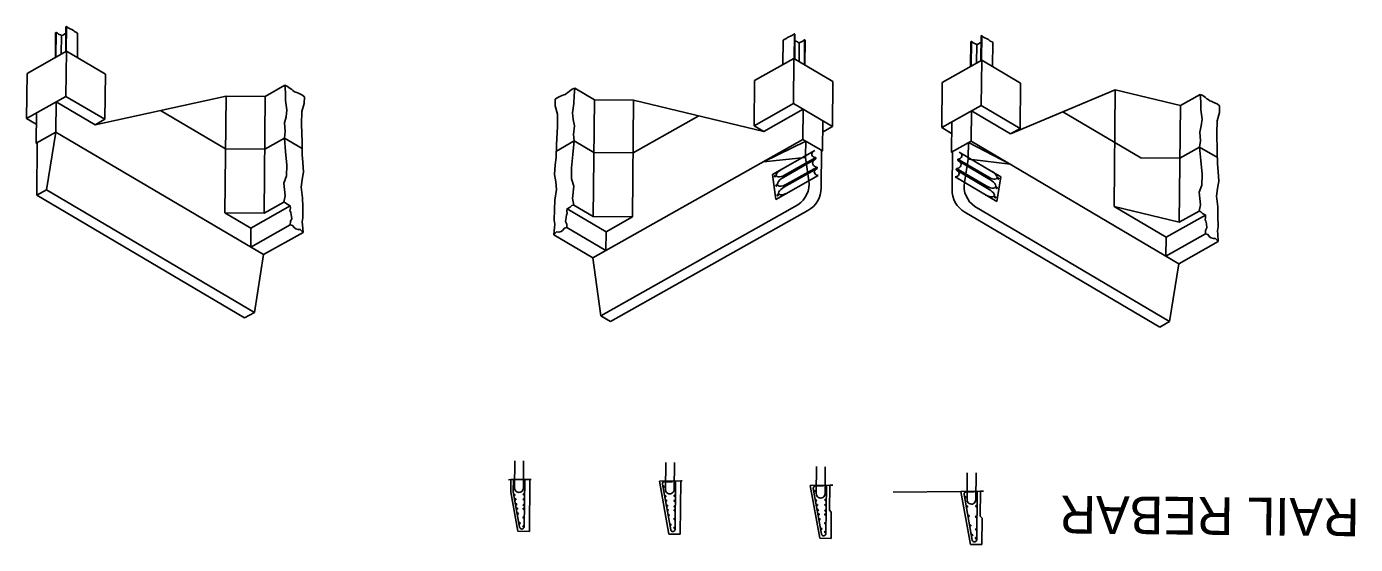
# Model space of a CAD drawing. Extents: x 631918 to 632319, y 373181 to 373282.
# Drawn here: x 631918.3 to 632006.4, y 373247.3 to 373281.7 of the extents above; entities that cross this region are included whole.
import ezdxf

# ---------------------------------------------------------------- set-up
doc = ezdxf.new("R2010")
doc.units = 0
for name, color, linetype in [('B_Boring', 7, 'Continuous'), ('BD-PROP-COSS', 7, 'Continuous'), ('BD-REMOVE', 7, 'Continuous'), ('R_Border_Scale', 7, 'Continuous'), ('R_Proposed Const Limits Cut', 7, 'Continuous'), ('R_Road Edge of Travel', 7, 'Continuous'), ('R_Shade Removal', 7, 'Continuous')]:
    doc.layers.add(name, color=color, linetype=linetype)

msp = doc.modelspace()

# ---------------------------------------------------------------- linework, layer by layer
at = {"layer": 'B_Boring'}
for p, q in [((631969.792, 373272.95), (631969.934, 373272.964)), ((631969.934, 373272.964), (631969.935, 373273.03)), ((631970.151, 373271.419), (631969.934, 373272.964)), ((631980.469, 373271.316), (631980.716, 373272.857)), ((631980.716, 373272.857), (631980.717, 373272.922)), ((631980.858, 373272.84), (631980.716, 373272.857))]:
    msp.add_line(p, q, dxfattribs=at)
at = {"layer": 'BD-PROP-COSS'}
for p, q in [((631950.664, 373252.836), (631950.646, 373251.044)), ((631951.247, 373252.83), (631951.229, 373251.038)), ((631960.663, 373252.736), (631960.645, 373250.945)), ((631961.247, 373252.73), (631961.229, 373250.939)), ((631970.661, 373252.454), (631970.643, 373250.663)), ((631971.244, 373252.449), (631971.226, 373250.657)), ((631980.657, 373252.052), (631980.64, 373250.261)), ((631981.241, 373252.047), (631981.223, 373250.255)), ((631950.56, 373250.791), (631950.568, 373251.599)), ((631951.287, 373248.474), (631951.318, 373251.591)), ((631960.452, 373251.286), (631960.996, 373248.267)), ((631961.121, 373251.452), (631960.597, 373251.457)), ((631961.286, 373248.292), (631961.318, 373251.492)), ((631971.119, 373251.171), (631970.595, 373251.176)), ((631971.283, 373248.01), (631971.315, 373251.21)), ((631950.56, 373250.791), (631950.982, 373248.447)), ((631970.45, 373251.004), (631970.994, 373247.985)), ((631980.447, 373250.602), (631980.991, 373247.583)), ((631981.115, 373250.768), (631980.592, 373250.774)), ((631981.28, 373247.608), (631981.312, 373250.808))]:
    msp.add_line(p, q, dxfattribs=at)
for centre in [(631950.606, 373251.211), (631951.274, 373251.329), (631960.528, 373251.112), (631961.273, 373251.23), (631950.641, 373250.586), (631950.693, 373250.293), (631951.263, 373250.288), (631951.267, 373250.621), (631960.64, 373250.486), (631960.693, 373250.194), (631961.263, 373250.188), (631961.266, 373250.522), (631970.525, 373250.831), (631970.638, 373250.205), (631971.264, 373250.24), (631971.271, 373250.948), (631980.522, 373250.429), (631981.267, 373250.546), (631950.753, 373249.96), (631950.806, 373249.667), (631950.865, 373249.333), (631951.257, 373249.663), (631951.26, 373249.913), (631960.753, 373249.86), (631960.805, 373249.568), (631961.257, 373249.563), (631961.259, 373249.813), (631970.69, 373249.912), (631970.75, 373249.578), (631971.257, 373249.532), (631971.261, 373249.907), (631980.634, 373249.802), (631981.26, 373249.838), (631950.978, 373248.707), (631951.246, 373248.496), (631951.251, 373249.08), (631960.865, 373249.234), (631960.977, 373248.608), (631961.251, 373248.98), (631970.803, 373249.286), (631970.863, 373248.952), (631971.249, 373248.698), (631971.254, 373249.282), (631980.747, 373249.176), (631980.859, 373248.55), (631981.253, 373249.13), (631961.245, 373248.397), (631970.975, 373248.326), (631971.243, 373248.115), (631980.972, 373247.924), (631981.239, 373247.713), (631981.245, 373248.296)]:
    msp.add_circle(centre, 0.0417, dxfattribs=at)
for centre, radius, start, end in [((631960.596, 373251.312), 0.146, 89.43036, 190.21458), ((631970.594, 373251.03), 0.146, 89.43036, 190.21458), ((631950.938, 373251.041), 0.292, 179.43036, 359.43036), ((631960.937, 373250.942), 0.292, 179.43036, 359.43036), ((631970.935, 373250.66), 0.292, 179.43036, 359.43036), ((631980.59, 373250.628), 0.146, 89.43036, 190.21458), ((631980.931, 373250.258), 0.292, 179.43036, 359.43036), ((631961.14, 373248.293), 0.146, 190.21458, 359.43036), ((631971.138, 373248.011), 0.146, 190.21458, 359.43036), ((631981.134, 373247.609), 0.146, 190.21458, 359.43036)]:
    msp.add_arc(centre, radius, start, end, dxfattribs=at)
msp.add_ellipse((631951.134, 373248.476), major_axis=(-0.002, -0.161), ratio=0.951273, start_param=4.900609, end_param=7.853982, dxfattribs=at)
at = {"layer": 'R_Border_Scale'}
for p, q in [((631931.485, 373273.544), (631927.18, 373276.087)), ((631992.156, 373272.941), (631986.99, 373275.992)), ((631958.498, 373273.275), (631962.853, 373275.732)), ((631934.083, 373273.518), (631935.39, 373274.255)), ((631936.563, 373273.562), (631935.39, 373274.255)), ((631953.422, 373273.395), (631954.608, 373274.064)), ((631955.9, 373273.301), (631954.608, 373274.064)), ((631931.485, 373273.544), (631934.083, 373273.518)), ((631958.498, 373273.275), (631955.9, 373273.301)), ((631994.754, 373272.915), (631996.061, 373273.652)), ((631997.234, 373272.959), (631996.061, 373273.652)), ((631992.156, 373272.941), (631994.754, 373272.915)), ((631950.403, 373251.591), (631951.664, 373251.604)), ((631960.246, 373251.49), (631961.663, 373251.504)), ((631970.244, 373251.209), (631971.536, 373251.222)), ((631980.24, 373250.806), (631981.532, 373250.819))]:
    msp.add_line(p, q, dxfattribs=at)
at = {"layer": 'R_Proposed Const Limits Cut'}
for p, q in [((631967.742, 373271.841), (631970.547, 373273.424)), ((631982.886, 373271.69), (631980.112, 373273.329)), ((631968.467, 373271.649), (631970.626, 373272.867)), ((631968.499, 373270.988), (631970.714, 373272.237)), ((631968.547, 373271.794), (631970.613, 373272.96)), ((631968.715, 373271.21), (631970.701, 373272.33)), ((631970.626, 373272.867), (631970.613, 373272.96)), ((631970.714, 373272.237), (631970.701, 373272.33)), ((631979.922, 373272.146), (631979.937, 373272.238)), ((631981.9, 373271.079), (631979.937, 373272.238)), ((631980.023, 373272.773), (631980.038, 373272.866)), ((631982.156, 373271.513), (631980.023, 373272.773)), ((631982.08, 373271.66), (631980.038, 373272.866)), ((631967.974, 373270.19), (631967.742, 373271.841)), ((631967.974, 373270.19), (631970.779, 373271.773)), ((631982.621, 373270.045), (631979.848, 373271.683)), ((631982.112, 373270.852), (631979.922, 373272.146)), ((631982.621, 373270.045), (631982.886, 373271.69))]:
    msp.add_line(p, q, dxfattribs=at)
for centre, major_axis, ratio, start_param, end_param in [((631970.616, 373273.188), (0.267, -0.005), 0.854896, 2.174054, 4.712811), ((631980.038, 373273.094), (0.267, -0.001), 0.854896, 4.711967, 7.250724), ((631970.705, 373272.594), (0.309, -0.005), 0.854896, 2.174054, 4.712811), ((631979.938, 373272.503), (0.309, -0.001), 0.854896, 4.711967, 7.250724), ((631968.44, 373271.984), (-0.44, -0.248), 0.432148, 4.712389, 7.853982), ((631968.591, 373271.43), (-0.508, -0.287), 0.432148, 4.712389, 7.853982), ((631970.783, 373272.002), (0.267, -0.005), 0.854896, 2.174054, 4.712811), ((631979.848, 373271.911), (0.267, -0.001), 0.854896, 4.711967, 7.250724), ((631982.028, 373271.296), (0.502, -0.297), 0.432148, 4.712389, 7.853982), ((631982.191, 373271.847), (0.435, -0.257), 0.432148, 4.712389, 7.853982), ((631968.606, 373270.798), (-0.44, -0.248), 0.432148, 4.712389, 7.853982), ((631982.001, 373270.664), (0.435, -0.257), 0.432148, 4.712389, 7.853982)]:
    msp.add_ellipse(centre, major_axis=major_axis, ratio=ratio, start_param=start_param, end_param=end_param, dxfattribs=at)
for centre, major_axis in [((631967.915, 373271.727), (-0.0216, -0.0437)), ((631968.539, 373271.74), (-0.0216, -0.0437)), ((631982.086, 373271.605), (0.0207, -0.0441)), ((631982.711, 373271.58), (0.0207, -0.0441)), ((631968.003, 373271.098), (-0.0216, -0.0437)), ((631968.091, 373270.468), (-0.0216, -0.0437)), ((631968.628, 373271.11), (-0.0216, -0.0437)), ((631981.985, 373270.978), (0.0207, -0.0441)), ((631982.61, 373270.952), (0.0207, -0.0441)), ((631982.509, 373270.325), (0.0207, -0.0441))]:
    msp.add_ellipse(centre, major_axis=major_axis, ratio=0.68171, dxfattribs=at)
at = {"layer": 'R_Road Edge of Travel'}
for p, q in [((631920.205, 373279.609), (631920.221, 373281.244)), ((631920.246, 373279.632), (631920.262, 373281.267)), ((631920.598, 373279.831), (631920.61, 373281.062)), ((631920.89, 373279.996), (631920.906, 373281.631)), ((631920.931, 373280.019), (631920.947, 373281.654)), ((631921.667, 373279.595), (631921.683, 373281.219)), ((631969.179, 373279.539), (631969.195, 373281.174)), ((631969.219, 373279.515), (631969.236, 373281.15)), ((631981.602, 373279.416), (631981.618, 373281.051)), ((631968.435, 373279.13), (631968.451, 373280.754)), ((631969.508, 373279.345), (631969.52, 373280.575)), ((631969.856, 373279.139), (631969.872, 373280.774)), ((631969.897, 373279.115), (631969.913, 373280.75)), ((631980.876, 373279.006), (631980.892, 373280.641)), ((631980.917, 373279.029), (631980.933, 373280.664)), ((631981.269, 373279.228), (631981.281, 373280.459)), ((631981.561, 373279.392), (631981.577, 373281.028)), ((631982.338, 373278.992), (631982.354, 373280.616))]:
    msp.add_line(p, q, dxfattribs=at)
for points in [[(631920.221, 373281.244), (631920.262, 373281.267), (631920.308, 373281.242), (631920.346, 373281.206), (631920.421, 373281.15), (631920.457, 373281.136), (631920.537, 373281.104), (631920.61, 373281.062), (631920.691, 373281.09), (631920.736, 373281.115), (631920.839, 373281.166), (631920.868, 373281.17), (631920.902, 373281.19)], [(631920.906, 373281.631), (631920.947, 373281.654), (631921.059, 373281.562), (631921.148, 373281.517), (631921.348, 373281.429), (631921.423, 373281.37), (631921.48, 373281.32), (631921.511, 373281.296), (631921.566, 373281.275), (631921.683, 373281.219)], [(631969.236, 373281.15), (631969.195, 373281.174), (631969.081, 373281.085), (631968.992, 373281.041), (631968.79, 373280.957), (631968.714, 373280.9), (631968.656, 373280.851), (631968.624, 373280.828), (631968.569, 373280.808), (631968.451, 373280.754)], [(631981.577, 373281.028), (631981.618, 373281.051), (631981.73, 373280.959), (631981.819, 373280.914), (631982.019, 373280.825), (631982.094, 373280.767), (631982.151, 373280.717), (631982.182, 373280.693), (631982.237, 373280.672), (631982.354, 373280.616)], [(631969.913, 373280.75), (631969.872, 373280.774), (631969.827, 373280.749), (631969.787, 373280.714), (631969.711, 373280.659), (631969.675, 373280.646), (631969.594, 373280.616), (631969.52, 373280.575), (631969.44, 373280.605), (631969.396, 373280.631), (631969.293, 373280.685), (631969.265, 373280.689), (631969.231, 373280.709)], [(631980.892, 373280.641), (631980.933, 373280.664), (631980.978, 373280.638), (631981.017, 373280.602), (631981.092, 373280.546), (631981.128, 373280.533), (631981.208, 373280.5), (631981.281, 373280.459), (631981.362, 373280.487), (631981.407, 373280.512), (631981.51, 373280.563), (631981.539, 373280.567), (631981.573, 373280.586)]]:
    msp.add_lwpolyline(points, dxfattribs=at)
at = {"layer": 'R_Shade Removal'}
for p, q in [((631918.328, 373278.55), (631920.941, 373280.024)), ((631920.911, 373277.024), (631920.941, 373280.024)), ((631923.524, 373278.498), (631920.941, 373280.024)), ((631966.557, 373278.071), (631969.169, 373279.545)), ((631969.14, 373276.545), (631969.169, 373279.545)), ((631971.753, 373278.019), (631969.169, 373279.545)), ((631978.999, 373277.947), (631981.612, 373279.421)), ((631981.582, 373276.421), (631981.612, 373279.421)), ((631984.195, 373277.895), (631981.612, 373279.421)), ((631918.298, 373275.55), (631918.328, 373278.55)), ((631923.494, 373275.499), (631923.524, 373278.498)), ((631934.118, 373277.018), (631935.425, 373277.755)), ((631955.935, 373276.801), (631954.643, 373277.564)), ((631966.527, 373275.071), (631966.557, 373278.071)), ((631971.723, 373275.019), (631971.753, 373278.019)), ((631978.969, 373274.947), (631978.999, 373277.947)), ((631984.165, 373274.895), (631984.195, 373277.895)), ((631918.298, 373275.55), (631920.911, 373277.024)), ((631920.238, 373274.656), (631920.258, 373276.656)), ((631922.841, 373275.13), (631920.258, 373276.656)), ((631923.494, 373275.499), (631920.911, 373277.024)), ((631931.52, 373277.044), (631922.841, 373275.13)), ((631931.52, 373277.044), (631931.443, 373269.294)), ((631931.52, 373277.044), (631934.118, 373277.018)), ((631934.118, 373277.018), (631934.041, 373269.268)), ((631955.935, 373276.801), (631955.858, 373269.052)), ((631958.533, 373276.775), (631955.935, 373276.801)), ((631958.533, 373276.775), (631958.456, 373269.026)), ((631958.533, 373276.775), (631967.173, 373274.689)), ((631990.469, 373277.458), (631983.511, 373274.527)), ((631990.469, 373277.458), (631990.392, 373269.708)), ((631990.469, 373277.458), (631994.789, 373276.415)), ((631994.789, 373276.415), (631996.096, 373277.152)), ((631918.931, 373273.919), (631918.951, 373275.919)), ((631966.527, 373275.071), (631969.14, 373276.545)), ((631967.173, 373274.689), (631969.785, 373276.163)), ((631971.723, 373275.019), (631969.14, 373276.545)), ((631969.766, 373274.164), (631969.785, 373276.163)), ((631978.969, 373274.947), (631981.582, 373276.421)), ((631980.909, 373274.053), (631980.928, 373276.053)), ((631983.511, 373274.527), (631980.928, 373276.053)), ((631984.165, 373274.895), (631981.582, 373276.421)), ((631994.789, 373276.415), (631994.712, 373268.665)), ((631918.944, 373275.169), (631918.298, 373275.55)), ((631922.841, 373275.13), (631923.494, 373275.499)), ((631967.173, 373274.689), (631966.527, 373275.071)), ((631971.057, 373273.401), (631971.077, 373275.401)), ((631971.069, 373274.651), (631971.723, 373275.019)), ((631979.615, 373274.566), (631978.969, 373274.947)), ((631979.602, 373273.316), (631979.622, 373275.316)), ((631983.511, 373274.527), (631984.165, 373274.895)), ((631918.931, 373273.919), (631920.238, 373274.656)), ((631919.622, 373270.829), (631920.238, 373274.656)), ((631934.014, 373266.519), (631920.238, 373274.656)), ((631955.83, 373266.302), (631969.766, 373274.164)), ((631967.153, 373272.689), (631969.945, 373274.058)), ((631971.057, 373273.401), (631969.766, 373274.164)), ((631969.935, 373273.078), (631969.945, 373274.058)), ((631979.602, 373273.316), (631980.909, 373274.053)), ((631994.685, 373265.915), (631980.909, 373274.053)), ((631919.003, 373273.876), (631918.931, 373273.919)), ((631918.969, 373270.46), (631919.004, 373273.96)), ((631970.96, 373270.943), (631970.985, 373273.443)), ((631970.984, 373273.36), (631971.057, 373273.401)), ((631979.674, 373273.273), (631979.602, 373273.316)), ((631979.65, 373270.857), (631979.675, 373273.357)), ((631980.717, 373272.971), (631980.727, 373273.95)), ((631983.492, 373272.527), (631980.727, 373273.95)), ((631967.153, 373272.689), (631969.69, 373272.94)), ((631983.492, 373272.527), (631980.96, 373272.828)), ((631918.969, 373270.46), (631919.622, 373270.829)), ((631933.398, 373262.691), (631919.622, 373270.829)), ((631932.745, 373262.323), (631918.969, 373270.46)), ((631933.165, 373268.277), (631935.778, 373269.751)), ((631934.041, 373269.268), (631935.348, 373270.005)), ((631955.858, 373269.052), (631954.566, 373269.814)), ((631956.369, 373262.463), (631969.434, 373269.833)), ((631994.069, 373262.088), (631981.154, 373269.717)), ((631990.392, 373269.708), (631994.712, 373268.665)), ((631993.836, 373267.674), (631990.392, 373269.708)), ((631933.165, 373268.277), (631931.443, 373269.294)), ((631931.443, 373269.294), (631934.041, 373269.268)), ((631956.714, 373268.043), (631954.131, 373269.569)), ((631958.456, 373269.026), (631955.858, 373269.052)), ((631956.714, 373268.043), (631958.456, 373269.026)), ((631957.015, 373262.081), (631970.08, 373269.452)), ((631993.416, 373261.719), (631980.501, 373269.348)), ((631993.836, 373267.674), (631996.449, 373269.148)), ((631994.712, 373268.665), (631996.019, 373269.402)), ((631933.153, 373267.027), (631935.766, 373268.501)), ((631933.165, 373268.277), (631933.153, 373267.027)), ((631934.014, 373266.519), (631936.627, 373267.993)), ((631956.701, 373266.793), (631954.118, 373268.319)), ((631956.714, 373268.043), (631956.701, 373266.793)), ((631993.836, 373267.674), (631992.114, 373268.691)), ((631993.824, 373266.424), (631996.437, 373267.898)), ((631955.83, 373266.302), (631953.247, 373267.827)), ((631993.836, 373267.674), (631993.824, 373266.424)), ((631994.685, 373265.915), (631997.298, 373267.389)), ((631933.398, 373262.691), (631934.014, 373266.519)), ((631956.369, 373262.463), (631955.83, 373266.302)), ((631994.069, 373262.088), (631994.685, 373265.915)), ((631932.745, 373262.323), (631933.398, 373262.691)), ((631957.015, 373262.081), (631956.369, 373262.463)), ((631993.416, 373261.719), (631994.069, 373262.088)), ((631950.247, 373251.59), (631950.403, 373251.591)), ((631950.395, 373250.768), (631950.403, 373251.591)), ((631951.629, 373248.159), (631951.664, 373251.604)), ((631951.664, 373251.604), (631951.747, 373251.605)), ((631960.246, 373251.49), (631960.878, 373247.984)), ((631961.628, 373247.976), (631961.663, 373251.504)), ((631961.663, 373251.504), (631961.746, 373251.505)), ((631970.244, 373251.209), (631970.876, 373247.702)), ((631971.519, 373249.571), (631971.536, 373251.222)), ((631971.536, 373251.222), (631971.744, 373251.224)), ((631950.395, 373250.768), (631950.864, 373248.167)), ((631975.739, 373250.761), (631980.24, 373250.806)), ((631980.24, 373250.806), (631980.872, 373247.3)), ((631981.516, 373249.169), (631981.532, 373250.819)), ((631981.532, 373250.819), (631981.74, 373250.821)), ((631971.643, 373249.445), (631971.519, 373249.571)), ((631971.626, 373247.695), (631971.643, 373249.445)), ((631981.64, 373249.042), (631981.516, 373249.169)), ((631981.622, 373247.293), (631981.64, 373249.042)), ((631950.864, 373248.167), (631951.629, 373248.159)), ((631960.878, 373247.984), (631961.628, 373247.976)), ((631970.876, 373247.702), (631971.626, 373247.695)), ((631980.872, 373247.3), (631981.622, 373247.293))]:
    msp.add_line(p, q, dxfattribs=at)
for points in [[(631936.627, 373267.993), (631936.442, 373268.192), (631936.306, 373268.194), (631936.146, 373268.235), (631936.051, 373268.3), (631936.051, 373268.3), (631935.933, 373268.461), (631935.933, 373268.461), (631935.766, 373268.501), (631935.784, 373268.716), (631935.873, 373268.91), (631935.873, 373268.91), (631935.836, 373269.166), (631935.806, 373269.334), (631935.759, 373269.431), (631935.784, 373269.598), (631935.778, 373269.751), (631935.579, 373269.864), (631935.46, 373269.962), (631935.46, 373269.962), (631935.348, 373270.005), (631935.438, 373270.433), (631935.362, 373271.26), (631935.529, 373271.74), (631935.55, 373272.468), (631935.461, 373273.364), (631935.39, 373274.255), (631935.447, 373274.68), (631935.4, 373275.255), (631935.498, 373275.674), (631935.558, 373276.121), (631935.467, 373276.738), (631935.459, 373277.27), (631935.425, 373277.755)], [(631936.716, 373276.992), (631936.55, 373277.125), (631936.363, 373277.203), (631936.147, 373277.297), (631936.066, 373277.333), (631935.953, 373277.41), (631935.875, 373277.471), (631935.778, 373277.548), (631935.592, 373277.683), (631935.425, 373277.755)], [(631953.247, 373267.827), (631953.436, 373268.023), (631953.572, 373268.022), (631953.732, 373268.06), (631953.829, 373268.123), (631953.829, 373268.123), (631953.95, 373268.282), (631953.95, 373268.282), (631954.118, 373268.319), (631954.105, 373268.534), (631954.019, 373268.729), (631954.019, 373268.729), (631954.061, 373268.985), (631954.095, 373269.152), (631954.144, 373269.248), (631954.121, 373269.416), (631954.131, 373269.569), (631954.332, 373269.678), (631954.453, 373269.773), (631954.453, 373269.773), (631954.566, 373269.814), (631954.484, 373270.244), (631954.576, 373271.069), (631954.419, 373271.552), (631954.413, 373272.28), (631954.519, 373273.175), (631954.608, 373274.064), (631954.559, 373274.49), (631954.618, 373275.064), (631954.528, 373275.484), (631954.477, 373275.933), (631954.581, 373276.548), (631954.599, 373277.079), (631954.643, 373277.564)], [(631953.337, 373276.827), (631953.506, 373276.956), (631953.694, 373277.03), (631953.912, 373277.121), (631953.994, 373277.155), (631954.108, 373277.23), (631954.188, 373277.289), (631954.286, 373277.364), (631954.475, 373277.495), (631954.643, 373277.564)], [(631936.716, 373276.992), (631936.71, 373276.559), (631936.542, 373276.009), (631936.52, 373275.178), (631936.561, 373273.986), (631936.565, 373273.138), (631936.62, 373272.649), (631936.666, 373271.992), (631936.568, 373271.514), (631936.507, 373271.003), (631936.598, 373270.298), (631936.604, 373269.69), (631936.611, 373268.97), (631936.566, 373268.699), (631936.566, 373268.699), (631936.589, 373268.491), (631936.627, 373267.993)], [(631953.337, 373276.827), (631953.335, 373276.393), (631953.491, 373275.841), (631953.497, 373275.009), (631953.432, 373273.819), (631953.411, 373272.971), (631953.347, 373272.483), (631953.287, 373271.827), (631953.376, 373271.347), (631953.427, 373270.835), (631953.322, 373270.132), (631953.304, 373269.524), (631953.282, 373268.805), (631953.322, 373268.532), (631953.322, 373268.532), (631953.295, 373268.325), (631953.247, 373267.827)], [(631997.298, 373267.389), (631997.113, 373267.589), (631996.977, 373267.59), (631996.817, 373267.632), (631996.722, 373267.697), (631996.722, 373267.697), (631996.604, 373267.858), (631996.604, 373267.858), (631996.437, 373267.898), (631996.454, 373268.113), (631996.544, 373268.306), (631996.544, 373268.306), (631996.507, 373268.563), (631996.477, 373268.731), (631996.43, 373268.828), (631996.455, 373268.995), (631996.449, 373269.148), (631996.25, 373269.261), (631996.131, 373269.358), (631996.131, 373269.358), (631996.019, 373269.402), (631996.109, 373269.83), (631996.033, 373270.657), (631996.2, 373271.137), (631996.221, 373271.865), (631996.132, 373272.761), (631996.061, 373273.652), (631996.118, 373274.077), (631996.071, 373274.652), (631996.169, 373275.07), (631996.229, 373275.518), (631996.138, 373276.134), (631996.13, 373276.666), (631996.096, 373277.152)], [(631997.387, 373276.389), (631997.221, 373276.522), (631997.034, 373276.599), (631996.818, 373276.694), (631996.737, 373276.73), (631996.624, 373276.807), (631996.545, 373276.868), (631996.448, 373276.945), (631996.262, 373277.08), (631996.096, 373277.152)], [(631997.387, 373276.389), (631997.381, 373275.955), (631997.213, 373275.406), (631997.191, 373274.575), (631997.232, 373273.383), (631997.236, 373272.535), (631997.291, 373272.046), (631997.337, 373271.389), (631997.239, 373270.911), (631997.178, 373270.4), (631997.268, 373269.695), (631997.275, 373269.087), (631997.282, 373268.367), (631997.237, 373268.096), (631997.237, 373268.096), (631997.259, 373267.887), (631997.298, 373267.389)]]:
    msp.add_lwpolyline(points, dxfattribs=at)
for centre, radius, start, end in [((631968.54, 373271.193), 1.627, 303.33523, 7.98399), ((631969.342, 373270.894), 1.62, 297.10598, 1.75474), ((631981.267, 373270.775), 1.62, 177.10598, 241.75474), ((631982.075, 373271.058), 1.627, 170.87673, 235.52548)]:
    msp.add_arc(centre, radius, start, end, dxfattribs=at)

# ---------------------------------------------------------------- texts
at = {"layer": 'BD-REMOVE'}
msp.add_text('RAIL REBAR', height=2.5, rotation=179.43036, dxfattribs=at).set_placement((632006.661, 373250.332))

doc.saveas('drawing.dxf')
